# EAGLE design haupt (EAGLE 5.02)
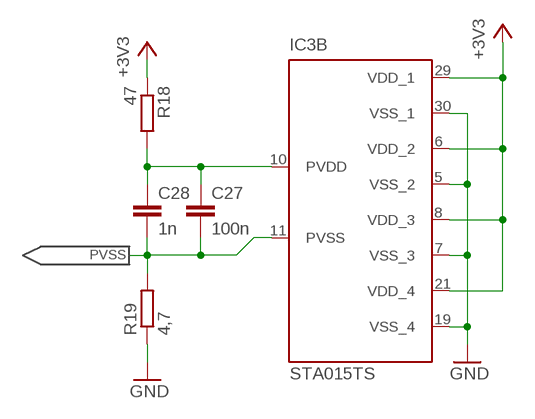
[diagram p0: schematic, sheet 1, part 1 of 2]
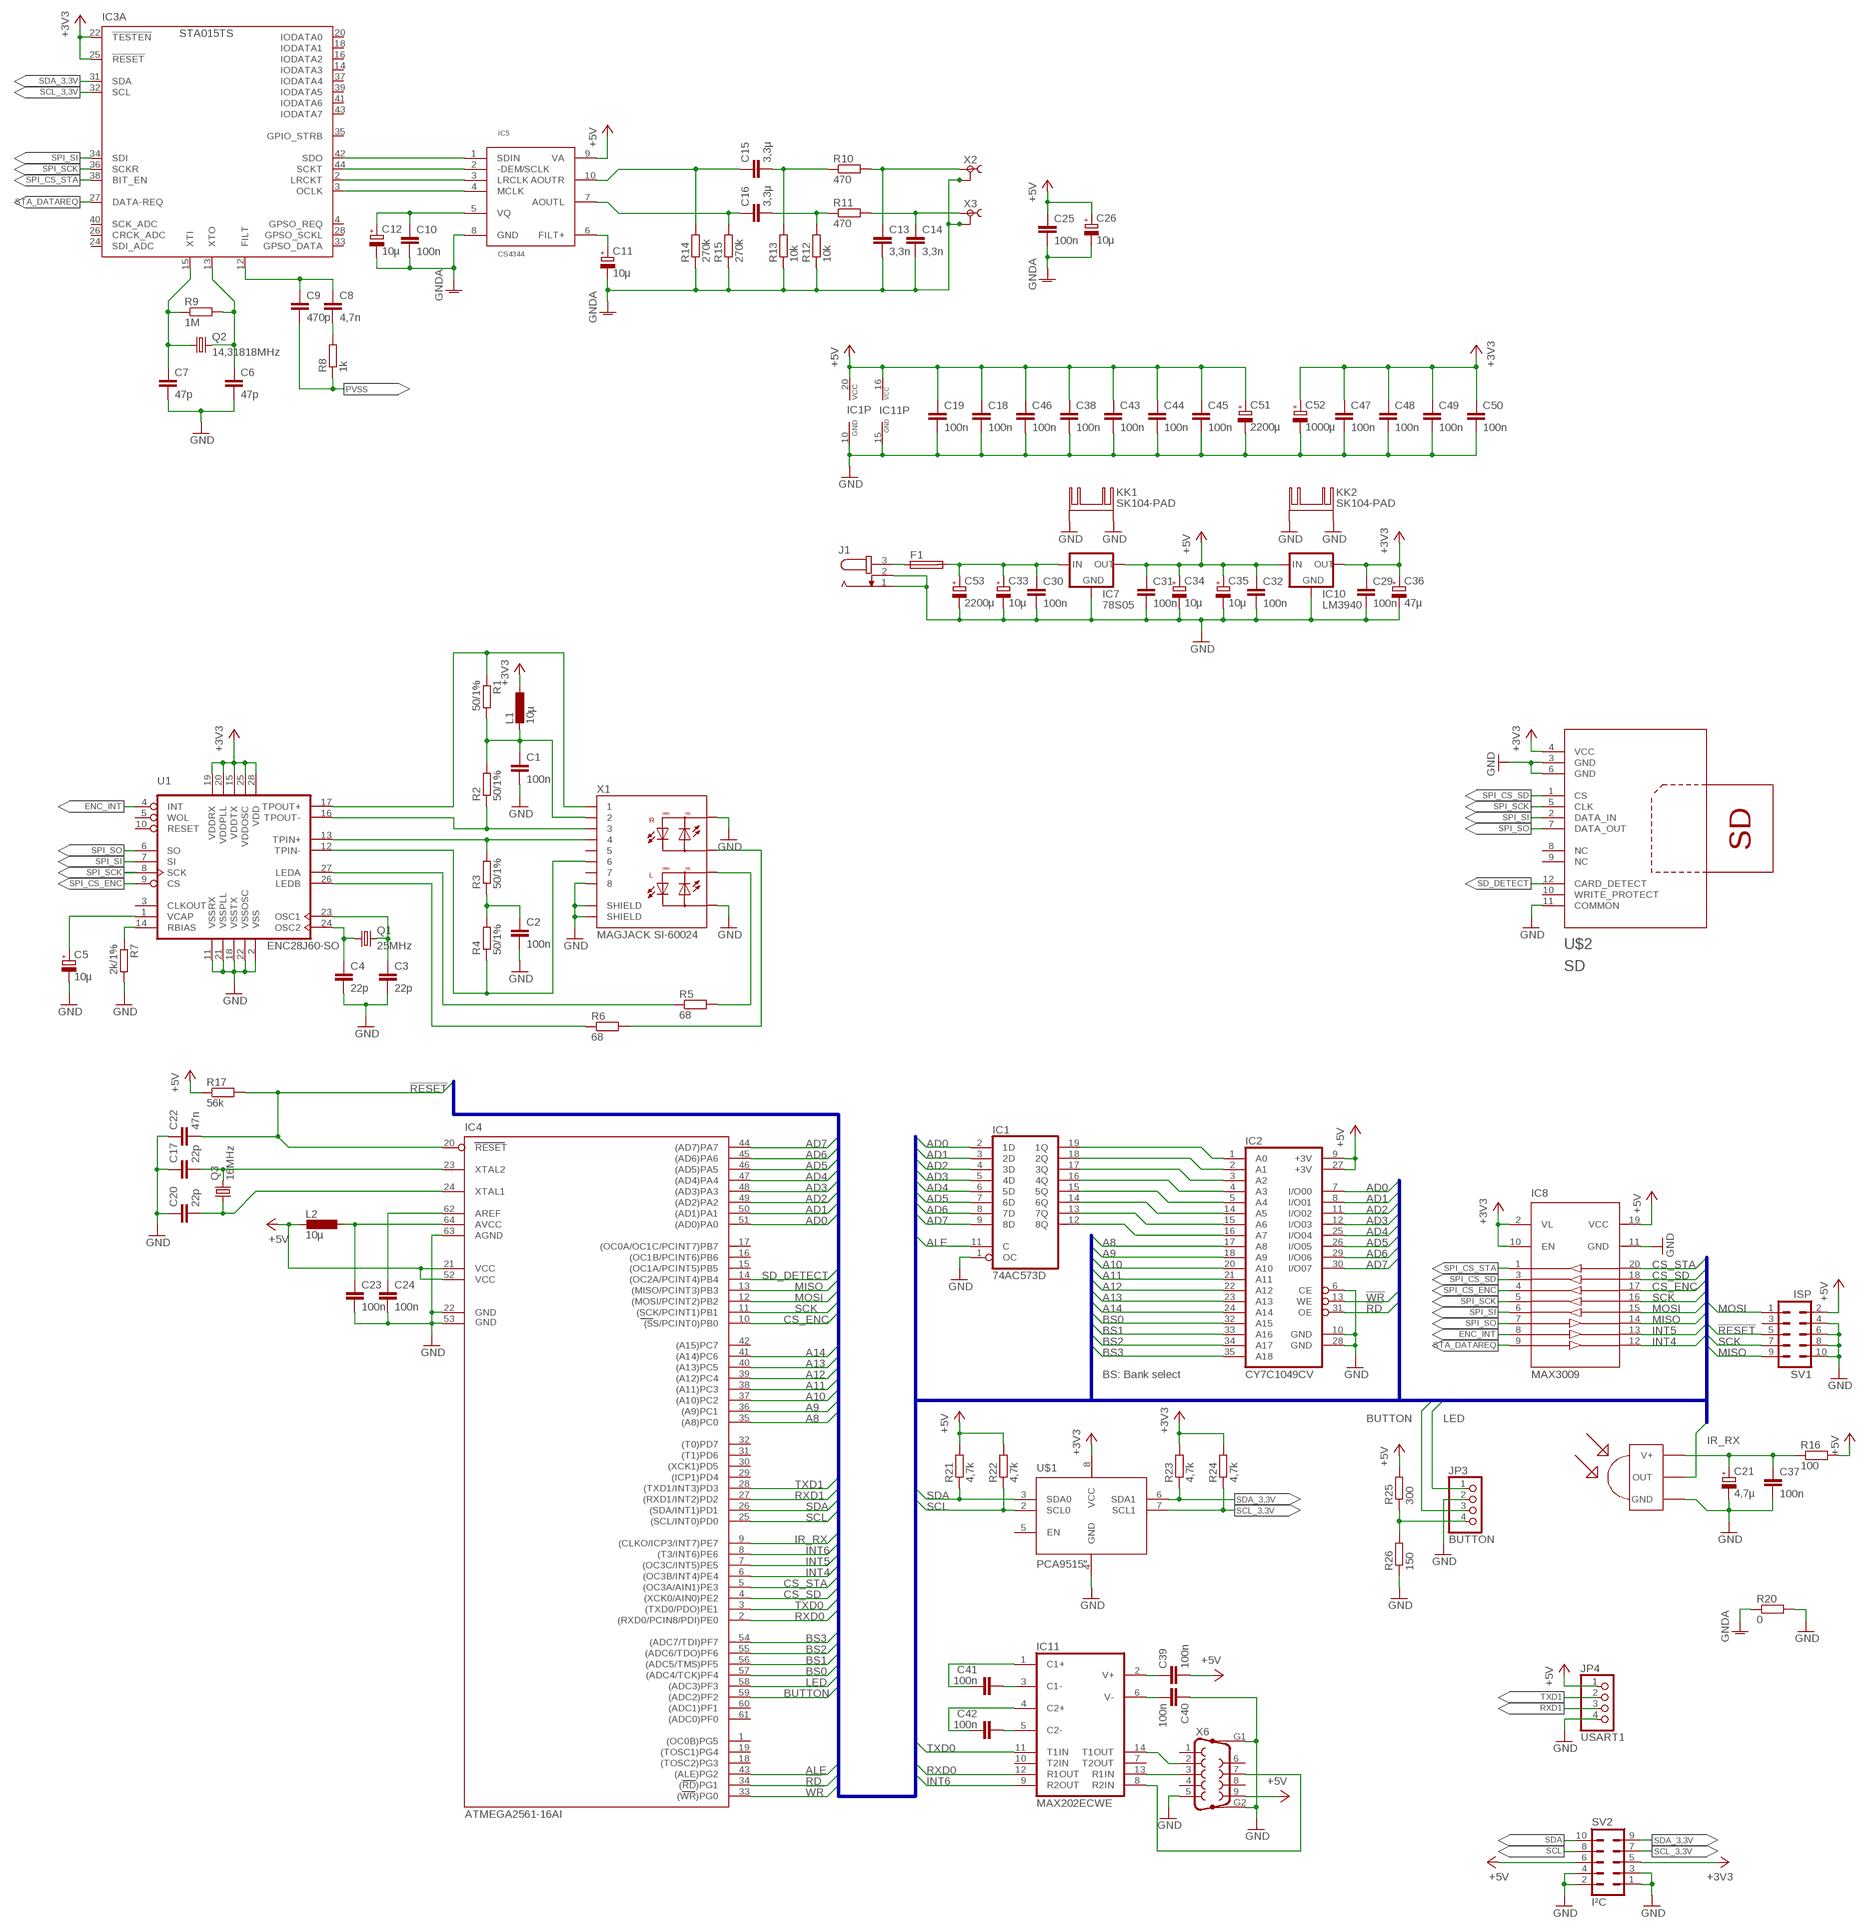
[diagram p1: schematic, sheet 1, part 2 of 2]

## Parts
C1  100n  C-EUC1206  [C1206]
C2  100n  C-EUC1206  [C1206]
C3  22p  C-EUC1206  [C1206]
C4  22p  C-EUC1206  [C1206]
C5  10µ  CPOL-EUE2-5  [E2-5]
C6  47p  C-EUC1206  [C1206]
C7  47p  C-EUC1206  [C1206]
C8  4,7n  C-EUC1206  [C1206]
C9  470p  C-EUC1206  [C1206]
C10  100n  C-EUC1206  [C1206]
C11  10µ  CPOL-EUE2-5  [E2-5]
C12  10µ  CPOL-EUE2-5  [E2-5]
C13  3,3n  C-EUC1206  [C1206]
C14  3,3n  C-EUC1206  [C1206]
C15  3,3µ  C-EUC1206  [C1206]
C16  3,3µ  C-EUC1206  [C1206]
C17  22p  C-EUC1206  [C1206]
C18  100n  C-EUC1206  [C1206]
C19  100n  C-EUC1206  [C1206]
C20  22p  C-EUC1206  [C1206]
C21  4,7µ  CPOL-EUE2-5  [E2-5]
C22  47n  C-EUC1206  [C1206]
C23  100n  C-EUC1206  [C1206]
C24  100n  C-EUC1206  [C1206]
C25  100n  C-EUC1206  [C1206]
C26  10µ  CPOL-EUE2-5  [E2-5]
C27  100n  C-EUC1206  [C1206]
C28  1n  C-EUC1206  [C1206]
C29  100n  C-EUC1206  [C1206]
C30  100n  C-EUC1206  [C1206]
C31  100n  C-EUC1206  [C1206]
C32  100n  C-EUC1206  [C1206]
C33  10µ  CPOL-EUE2-5  [E2-5]
C34  10µ  CPOL-EUE2-5  [E2-5]
C35  10µ  CPOL-EUE2-5  [E2-5]
C36  47µ  CPOL-EUE2-5  [E2-5]
C37  100n  C-EUC1206  [C1206]
C38  100n  C-EUC1206  [C1206]
C39  100n  C-EUC1206  [C1206]
C40  100n  C-EUC1206  [C1206]
C41  100n  C-EUC1206  [C1206]
C42  100n  C-EUC1206  [C1206]
C43  100n  C-EUC1206  [C1206]
C44  100n  C-EUC1206  [C1206]
C45  100n  C-EUC1206  [C1206]
C46  100n  C-EUC1206  [C1206]
C47  100n  C-EUC1206  [C1206]
C48  100n  C-EUC1206  [C1206]
C49  100n  C-EUC1206  [C1206]
C50  100n  C-EUC1206  [C1206]
C51  2200µ  CPOL-EUE5-13  [E5-13]
C52  1000µ  CPOL-EUE5-13  [E5-13]
C53  2200µ  CPOL-EUE5-13  [E5-13]
F1  SH22,5  [SH22,5]
IC1  74AC573D  [SO20W]
IC2  CY7C1049CV  CY7C1049CV33  [SOJV36-400]
IC3  STA015TS  [TQFP44]
IC4  ATMEGA2561-16AI  [TQFP64]
IC5  CS4344  [MSOP10]
IC7  78S05  78XXS  [78XXS]
IC8  MAX3009  [TSSOP20]
IC10  LM3940  78XXS  [78XXS]
IC11  MAX202ECWE  [SO16L]
J1  JACK-PLUG0  [SPC4077]
JP3  BUTTON  PINHD-1X4  [1X04]
JP4  USART1  PINHD-1X4  [1X04]
KK1  SK104-PAD  [SK104-PAD]
KK2  SK104-PAD  [SK104-PAD]
L1  10µ  L-EUL2825P  [L2825P]
L2  10µ  L-EUL2825P  [L2825P]
Q1  25MHz  CRYSTALHC49S  [HC49/S]
Q2  14,31818MHz  CRYSTALHC49S  [HC49/S]
Q3  16MHz  CRYSTALHC49S  [HC49/S]
R1  50/1%  R-EU_0207/2V  [0207/2V]
R2  50/1%  R-EU_0207/2V  [0207/2V]
R3  50/1%  R-EU_0207/2V  [0207/2V]
R4  50/1%  R-EU_0207/2V  [0207/2V]
R5  68  R-EU_R1206  [R1206]
R6  68  R-EU_R1206  [R1206]
R7  2k/1%  R-EU_0207/2V  [0207/2V]
R8  1k  R-EU_R1206  [R1206]
R9  1M  R-EU_R1206  [R1206]
R10  470  R-EU_R1206  [R1206]
R11  470  R-EU_R1206  [R1206]
R12  10k  R-EU_R1206  [R1206]
R13  10k  R-EU_R1206  [R1206]
R14  270k  R-EU_R1206  [R1206]
R15  270k  R-EU_R1206  [R1206]
R16  100  R-EU_R1206  [R1206]
R17  56k  R-EU_R1206  [R1206]
R18  47  R-EU_R1206  [R1206]
R19  4,7  R-EU_R1206  [R1206]
R20  0  R-EU_R1206  [R1206]
R21  4,7k  R-EU_R1206  [R1206]
R22  4,7k  R-EU_R1206  [R1206]
R23  4,7k  R-EU_R1206  [R1206]
R24  4,7k  R-EU_R1206  [R1206]
R25  300  R-EU_R1206  [R1206]
R26  150  R-EU_R1206  [R1206]
SV1  ISP  ML10  [ML10]
SV2  I²C  ML10  [ML10]
U1  ENC28J60-SO  [SO28W]
U$1  PCA9515"  [SO08]
U$2  SD  [SD]
U$3  TSOP1738  [TSOP17XX]
X1  MAGJACK SI-60024  SI-60024  [SI-60024]
X2  TOBU3  [TOBU3]
X3  TOBU3  [TOBU3]
X6  F09HP  [F09HP]

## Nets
!RD: IC2.31(OE) IC4.34((RD)PG1)
!RESET: C22.2 IC4.20(RESET) R17.2 SV1.5
!WR: IC2.13(WE) IC4.33((WR)PG0)
+3V3: C29.1 C36.+ C47.1 C48.1 C49.1 C50.1 C52.+ IC3.6(B:VDD_2) IC3.8(B:VDD_3) IC3.21(B:VDD_4) IC3.22(A:!TESTEN) IC3.25(A:!RESET) IC3.29(B:VDD_1) IC8.2(VL) IC8.10(EN) IC10.OUT L1.1 R18.1 R23.2 R24.2 SV2.5 U1.15(VDDTX) U1.19(VDDRX) U1.20(VDDPLL) U1.25(VDDOSC) U1.28(VDD) U$1.8(VCC) U$2.4(VCC)
+5V: C18.1 C19.1 C25.1 C26.+ C31.1 C32.1 C34.+ C35.+ C38.1 C39.2 C43.1 C44.1 C45.1 C46.1 C51.+ IC1.20(VCC) IC2.9(+3V) IC2.27(+3V) IC4.21(VCC) IC4.52(VCC1) IC5.9(VA) IC7.OUT IC8.19(VCC) IC10.IN IC11.16(VCC) JP4.1 L2.2 R16.2 R17.1 R21.2 R22.2 R25.2 SV1.2 SV2.6 X6.9
A8: IC2.17(A8) IC4.35((A8)PC0)
A9: IC2.18(A9) IC4.36((A9)PC1)
A10: IC2.20(A10) IC4.37((A10)PC2)
A11: IC2.21(A11) IC4.38((A11)PC3)
A12: IC2.22(A12) IC4.39((A12)PC4)
A13: IC2.23(A13) IC4.40((A13)PC5)
A14: IC2.24(A14) IC4.41((A14)PC6)
AD0: IC1.2(1D) IC2.7(I/O00) IC4.51((AD0)PA0)
AD1: IC1.3(2D) IC2.8(I/O01) IC4.50((AD1)PA1)
AD2: IC1.4(3D) IC2.11(I/O02) IC4.49((AD2)PA2)
AD3: IC1.5(4D) IC2.12(I/O03) IC4.48((AD3)PA3)
AD4: IC1.6(5D) IC2.25(I/O04) IC4.47((AD4)PA4)
AD5: IC1.7(6D) IC2.26(I/O05) IC4.46((AD5)PA5)
AD6: IC1.8(7D) IC2.29(I/O06) IC4.45((AD6)PA6)
AD7: IC1.9(8D) IC2.30(I/O07) IC4.44((AD7)PA7)
ALE: IC1.11(C) IC4.43((ALE)PG2)
BS0: IC2.32(A15) IC4.57((ADC4/TCK)PF4)
BS1: IC2.33(A16) IC4.56((ADC5/TMS)PF5)
BS2: IC2.34(A17) IC4.55((ADC6/TDO)PF6)
BS3: IC2.35(A18) IC4.54((ADC7/TDI)PF7)
BUTTON: IC4.59((ADC2)PF2) JP3.3
CS_ENC: IC4.10((SS/PCINT0)PB0) IC8.17(VCC3)
CS_SD: IC4.4((XCK0/AIN0)PE2) IC8.18(VCC2)
CS_STA: IC4.5((OC3A/AIN1)PE3) IC8.20(VCC1)
ENC_INT: IC8.8(VL7) U1.4(INT)
GND: C1.2 C2.2 C3.2 C4.2 C5.- C6.2 C7.2 C17.1 C18.2 C19.2 C20.1 C21.- C22.1 C23.2 C24.2 C29.2 C30.2 C31.2 C32.2 C33.- C34.- C35.- C36.- C37.2 C38.2 C40.1 C43.2 C44.2 C45.2 C46.2 C47.2 C48.2 C49.2 C50.2 C51.- C52.- C53.- IC1.1(OC) IC1.10(GND) IC2.6(CE) IC2.10(GND) IC2.28(GND) IC3.5(B:VSS_2) IC3.7(B:VSS_3) IC3.19(B:VSS_4) IC3.30(B:VSS_1) IC4.22(GND) IC4.53(GND1) IC4.63(AGND) IC7.GND IC8.11(GND) IC10.GND IC11.15(GND) J1.1 J1.2 JP3.2 JP4.4 KK1.K1(K) KK1.K2(K) KK2.K1(K) KK2.K2(K) R7.2 R19.1 R20.2 R26.1 SV1.4 SV1.6 SV1.8 SV1.10 SV2.1 SV2.2 SV2.3 SV2.4 U1.2(VSS) U1.11(VSSRX) U1.18(VSSTX) U1.21(VSSPLL) U1.22(VSSOSC) U$1.4(GND) U$2.3(GND) U$2.6(GND) U$2.11(COMMON) U$3.GND X1.8 X1.L_YEL_A X1.R_GRN_A X1.SCHIELD@2(SHIELD) X1.SHIELD@1(SHIELD) X6.5 X6.G1 X6.G2
GNDA: C10.2 C11.- C12.- C13.2 C14.2 C25.2 C26.- IC5.8(GND) R12.1 R13.1 R14.1 R15.1 R20.1 X2.2 X2.2@1 X2.2@2 X3.2 X3.2@1 X3.2@2
INT4: IC4.6((OC3B/INT4)PE4) IC8.12(VCC8)
INT5: IC4.7((OC3C/INT5)PE5) IC8.13(VCC7)
INT6: IC4.8((T3/INT6)PE6) IC11.9(R2OUT)
IR_RX: IC4.9((CLKO/ICP3/INT7)PE7) U$3.OUT
LED: IC4.58((ADC3)PF3) JP3.1
MISO: IC4.13((MISO/PCINT3)PB3) IC8.14(VCC6) SV1.9
MOSI: IC4.12((MOSI/PCINT2)PB2) IC8.15(VCC5) SV1.1
N$1: IC1.19(1Q) IC2.1(A0)
N$2: IC1.18(2Q) IC2.2(A1)
N$3: IC1.17(3Q) IC2.3(A2)
N$4: IC1.16(4Q) IC2.4(A3)
N$5: IC1.15(5Q) IC2.5(A4)
N$6: IC1.14(6Q) IC2.14(A5)
N$7: IC1.13(7Q) IC2.15(A6)
N$8: IC1.12(8Q) IC2.16(A7)
N$9: R1.1 U1.17(TPOUT+) X1.1
N$10: R2.1 U1.16(TPOUT-) X1.3
N$11: R3.2 U1.13(TPIN+) X1.4
N$12: R4.1 U1.12(TPIN-) X1.6
N$13: C1.1 L1.2 R1.2 R2.2 X1.2
N$14: R6.2 X1.R_YEL_A
N$15: C2.1 R3.1 R4.2
N$16: R5.1 U1.27(LEDA)
N$17: R6.1 U1.26(LEDB)
N$18: R5.2 X1.L_GRN_A
N$19: C4.1 Q1.1 U1.24(OSC2)
N$20: C3.1 Q1.2 U1.23(OSC1)
N$21: R7.1 U1.14(RBIAS)
N$22: C5.+ U1.1(VCAP)
N$23: F1.1 J1.3
N$24: IC11.8(R2IN) X6.7
N$25: C7.1 IC3.15(A:XTI) Q2.1 R9.1
N$26: C6.1 IC3.13(A:XTO) Q2.2 R9.2
N$27: C8.1 C9.1 IC3.12(A:FILT)
N$28: IC3.42(A:SDO) IC5.1(SDIN)
N$29: IC3.44(A:SCKT) IC5.2(-DEM/SCLK)
N$30: IC3.2(A:LRCKT) IC5.3(LRCLK)
N$31: IC3.3(A:OCLK) IC5.4(MCLK)
N$32: C8.2 R8.2
N$33: C10.1 C12.+ IC5.5(VQ)
N$34: C11.+ IC5.6(FILT+)
N$35: C14.1 R11.2 X3.1
N$36: C13.1 R10.2 X2.1
N$37: C17.2 IC4.23(XTAL2) Q3.2
N$38: C15.2 R10.1 R13.2
N$39: C16.2 R11.1 R12.2
N$40: C15.1 IC5.10(AOUTR) R14.2
N$41: C16.1 IC5.7(AOUTL) R15.2
N$42: JP3.4 R25.1 R26.2
N$44: C20.2 IC4.24(XTAL1) Q3.1
N$45: C21.+ C37.1 R16.1 U$3.V+
N$47: C23.1 IC4.64(AVCC) L2.1
N$48: C27.1 C28.1 IC3.10(B:PVDD) R18.2
N$49: C24.1 IC4.62(AREF)
N$51: C30.1 C33.+ C53.+ F1.2 IC7.IN
N$56: C41.2 IC11.1(C1+)
N$57: C41.1 IC11.3(C1-)
N$58: C42.2 IC11.4(C2+)
N$59: C42.1 IC11.5(C2-)
N$60: C39.1 IC11.2(V+)
N$61: C40.2 IC11.6(V-)
N$62: IC11.14(T1OUT) X6.2
N$63: IC11.13(R1IN) X6.3
PVSS: C9.2 C27.2 C28.2 IC3.11(B:PVSS) R8.1 R19.2
RXD0: IC4.2((RXD0/PCIN8/PDI)PE0) IC11.12(R1OUT)
RXD1: IC4.27((RXD1/INT2)PD2) JP4.3
SCK: IC4.11((SCK/PCINT1)PB1) IC8.16(VCC4) SV1.7
SCL: IC4.25((SCL/INT0)PD0) R22.1 SV2.8 U$1.2(SCL0)
SCL_3,3V: IC3.32(A:SCL) R24.1 SV2.7 U$1.7(SCL1)
SD_DETECT: IC4.14((OC2A/PCINT4)PB4) U$2.12(CARD_DETECT)
SDA: IC4.26((SDA/INT1)PD1) R21.1 SV2.10 U$1.3(SDA0)
SDA_3,3V: IC3.31(A:SDA) R23.1 SV2.9 U$1.6(SDA1)
SPI_CS_ENC: IC8.4(VL3) U1.9(CS)
SPI_CS_SD: IC8.3(VL2) U$2.1(CS)
SPI_CS_STA: IC3.38(A:BIT_EN) IC8.1(VL1)
SPI_SCK: IC3.36(A:SCKR) IC8.5(VL4) U1.8(SCK) U$2.5(CLK)
SPI_SI: IC3.34(A:SDI) IC8.6(VL5) U1.7(SI) U$2.2(DATA_IN)
SPI_SO: IC8.7(VL6) U1.6(SO) U$2.7(DATA_OUT)
STA_DATAREQ: IC3.27(A:DATA-REQ) IC8.9(VL8)
TXD0: IC4.3((TXD0/PDO)PE1) IC11.11(T1IN)
TXD1: IC4.28((TXD1/INT3)PD3) JP4.2
Unconnected: IC3.1(NC1:NC) IC3.4(A:GPSO_REQ) IC3.9(NC2:NC) IC3.14(A:IODATA3) IC3.16(A:IODATA2) IC3.17(NC3:NC) IC3.18(A:IODATA1) IC3.20(A:IODATA0) IC3.23(NC4:NC) IC3.24(A:SDI_ADC) IC3.26(A:CRCK_ADC) IC3.28(A:GPSO_SCKL) IC3.33(A:GPSO_DATA) IC3.35(A:GPIO_STRB) IC3.37(A:IODATA4) IC3.39(A:IODATA5) IC3.40(A:SCK_ADC) IC3.41(A:IODATA6) IC3.43(A:IODATA7) IC4.1((OC0B)PG5) IC4.15((OC1A/PCINT5)PB5) IC4.16((OC1B/PCINT6)PB6) IC4.17((OC0A/OC1C/PCINT7)PB7) IC4.18((TOSC2)PG3) IC4.19((TOSC1)PG4) IC4.29((ICP1)PD4) IC4.30((XCK1)PD5) IC4.31((T1)PD6) IC4.32((T0)PD7) IC4.42((A15)PC7) IC4.60((ADC1)PF1) IC4.61((ADC0)PF0) IC11.7(T2OUT) IC11.10(T2IN) SV1.3 U1.3(CLKOUT) U1.5(WOL) U1.10(RESET) U$1.5(EN) U$2.8(NC) U$2.9(NC) U$2.10(WRITE_PROTECT) X1.5 X1.7 X6.1 X6.4 X6.6 X6.8

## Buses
AD[0..7],ALE,!RD,!WR,A[8..14],BS[0..3],MOSI,MISO,SCK,SDA,SCL,RXD0,TXD0,RXD1,TXD1,CS_STA,CS_SD,CS_ENC,!RESET,INT2,INT4,INT5,INT6,IR_RX,SD_DETECT,LED,BUTTON

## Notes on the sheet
- BS: Bank select

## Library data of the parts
C1-C4 C6-C10 C13-C20 C22-C25 C27-C32 C37-C50 = rcl:C-EU: CAPACITOR, European symbol
C5 C11 C12 C21 C26 C33-C36 C51-C53 = rcl:CPOL-EU: POLARIZED CAPACITOR, European symbol
F1 = fuse:SH22,5: FUSE HOLDER
IC1 = 74xx-eu:74*573: 8-bit D latch BUS DRIVER
IC2 = memory-sram:CY7C1049CV33: 4-Mbit (512K x 8) Static RAM Source: CYPRESS cy7c1049cv33_8.pdf
IC3 = st-microelectronics:STA015TS: MP3 AUDIO DECODER with ADPCM capability
IC4 = atmel-2005:ATMEGA2561*: MICROCONTROLLER 256 Kbytes FLASH 4 Kbytes EEPROM 8 Kbytes SRAM 54 General Purpose I/O pins 6-channels 16-bit PWM 2 x Serial USARTs 8-channels 10-bit A/D
IC5 = cirrus-3:CS4344
IC7 IC10 = v-reg:78XXS: VOLTAGE REGULATOR
IC8 = maxim:MAX3009: +1.2V to +5.5V, ±15kV ESD-Protected, 0.1?A, 35Mbps, 8-Channel Level Translators
IC11 = maxim:MAX202ECWE: RS232 TRANSEIVER
J1 = con-jack:JACK-PLUG: DC POWER JACK Power Jack, DC, Right Angle, Through Hole, Rated 5A at 16VDC, PC Terminals Distributor: Farnell (www.Farnell.de) Drawing: 84N1161.pdf / 84N1162.pdf Manufacturer: SPC Technology (www.spctechnology.com) Type: SPC4077 / SPC 4078
JP3 JP4 = pinhead:PINHD-1X4: PIN HEADER
KK1 KK2 = heatsink:SK104-PAD: HEATSINK
L1 L2 = rcl:L-EU: INDUCTOR, European symbol
Q1-Q3 = crystal:CRYSTAL: CRYSTAL
R1-R26 = rcl:R-EU_: RESISTOR, European symbol
SV1 SV2 = con-harting-ml:ML10: HARTING
U1 = microchip-enc28j60:ENC28J60-*: Microchip 10Mbit Eth. contoller with SPI interface
U$1 = micro-philips:PCA9515: I2C bus repeater
U$2 = sd:SD
U$3 = tsop:TSOP1738: IR Receiver and Demodulator
X1 = si-50014:SI-60024
X2 X3 = con-hirschmann:TOBU3: Female Cinch CONNECTOR ( RCA Jack )
X6 = con-subd:F09HP: SUB-D

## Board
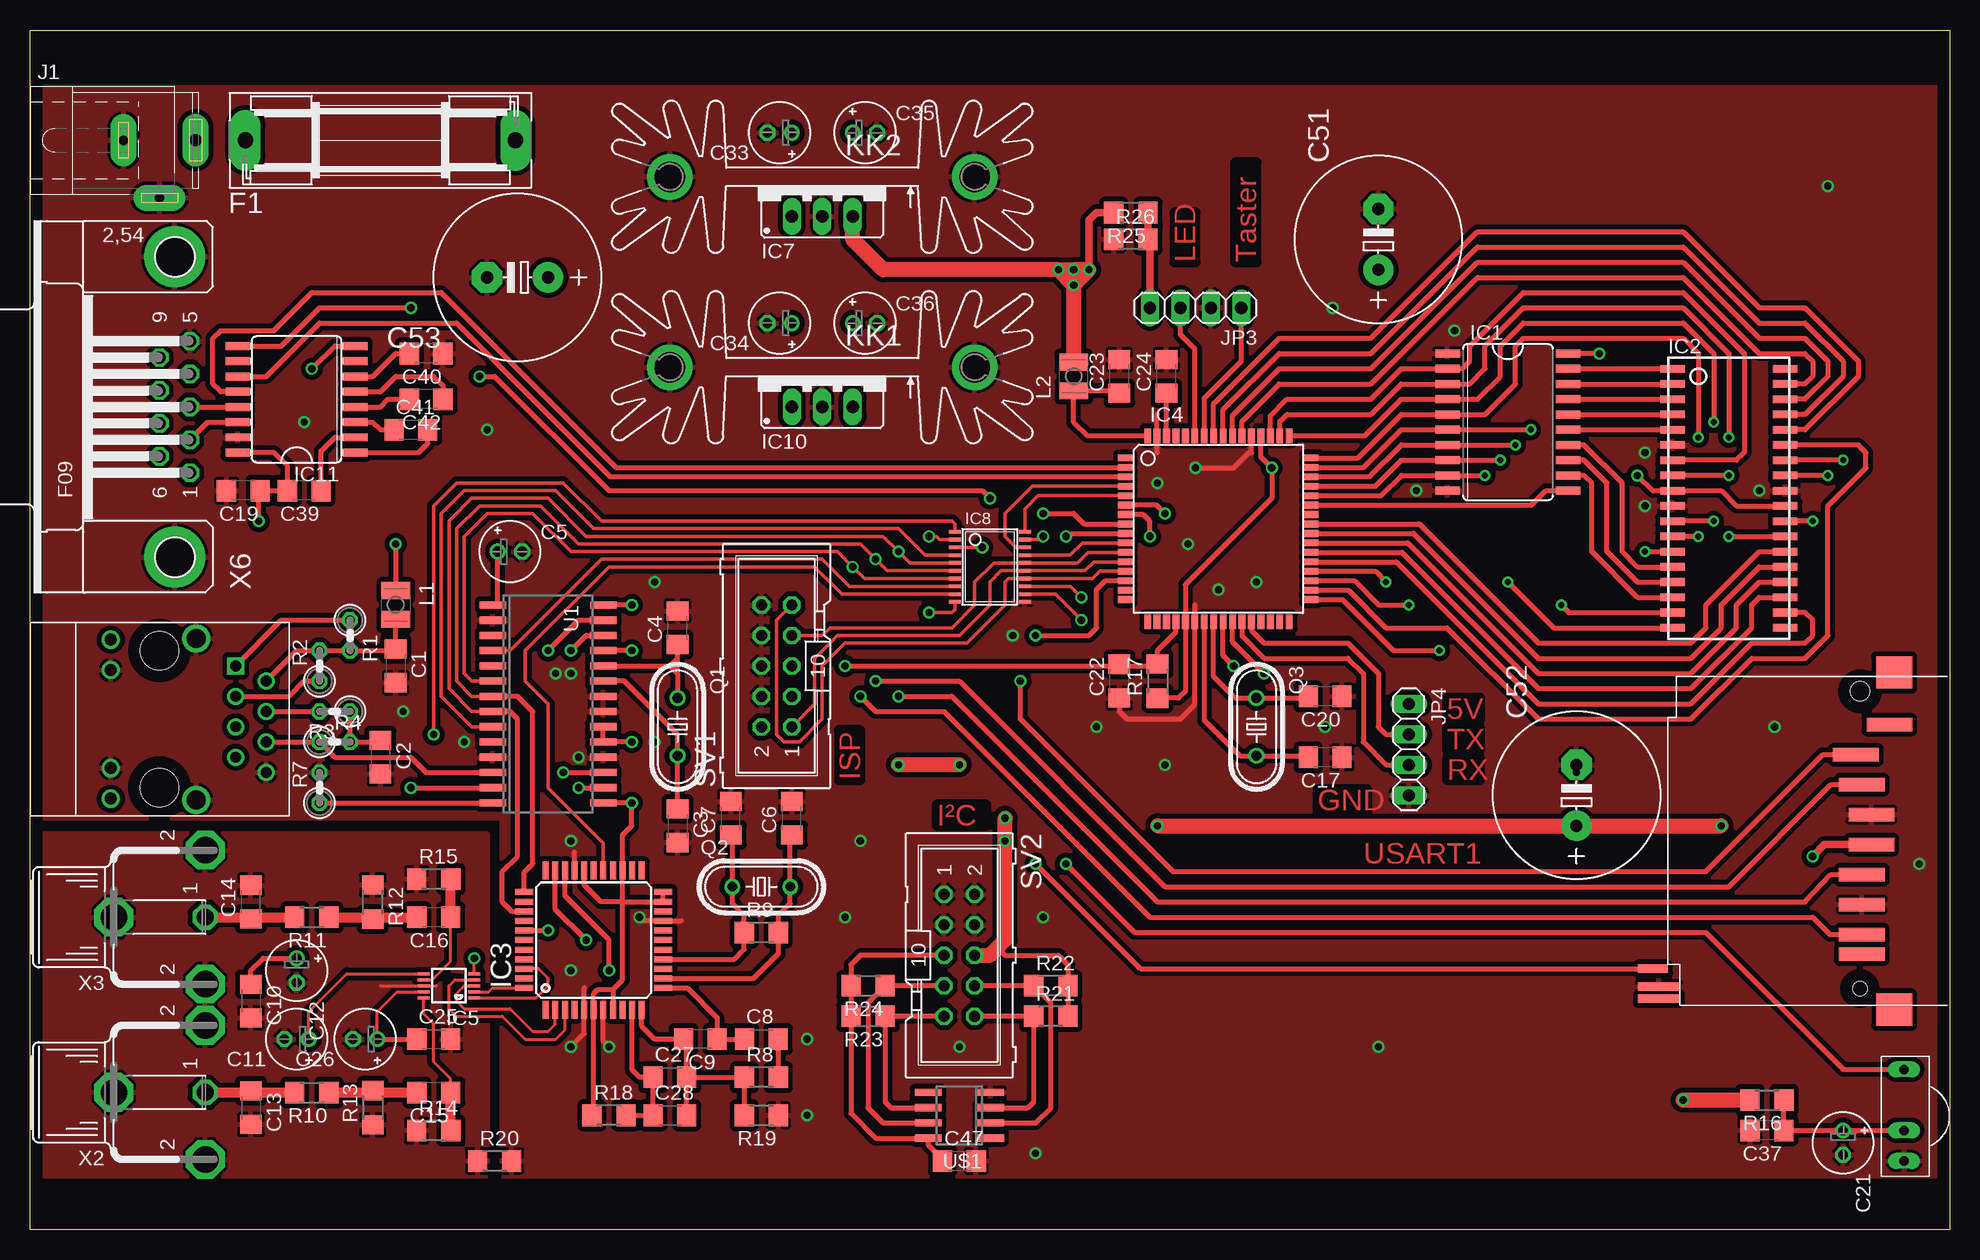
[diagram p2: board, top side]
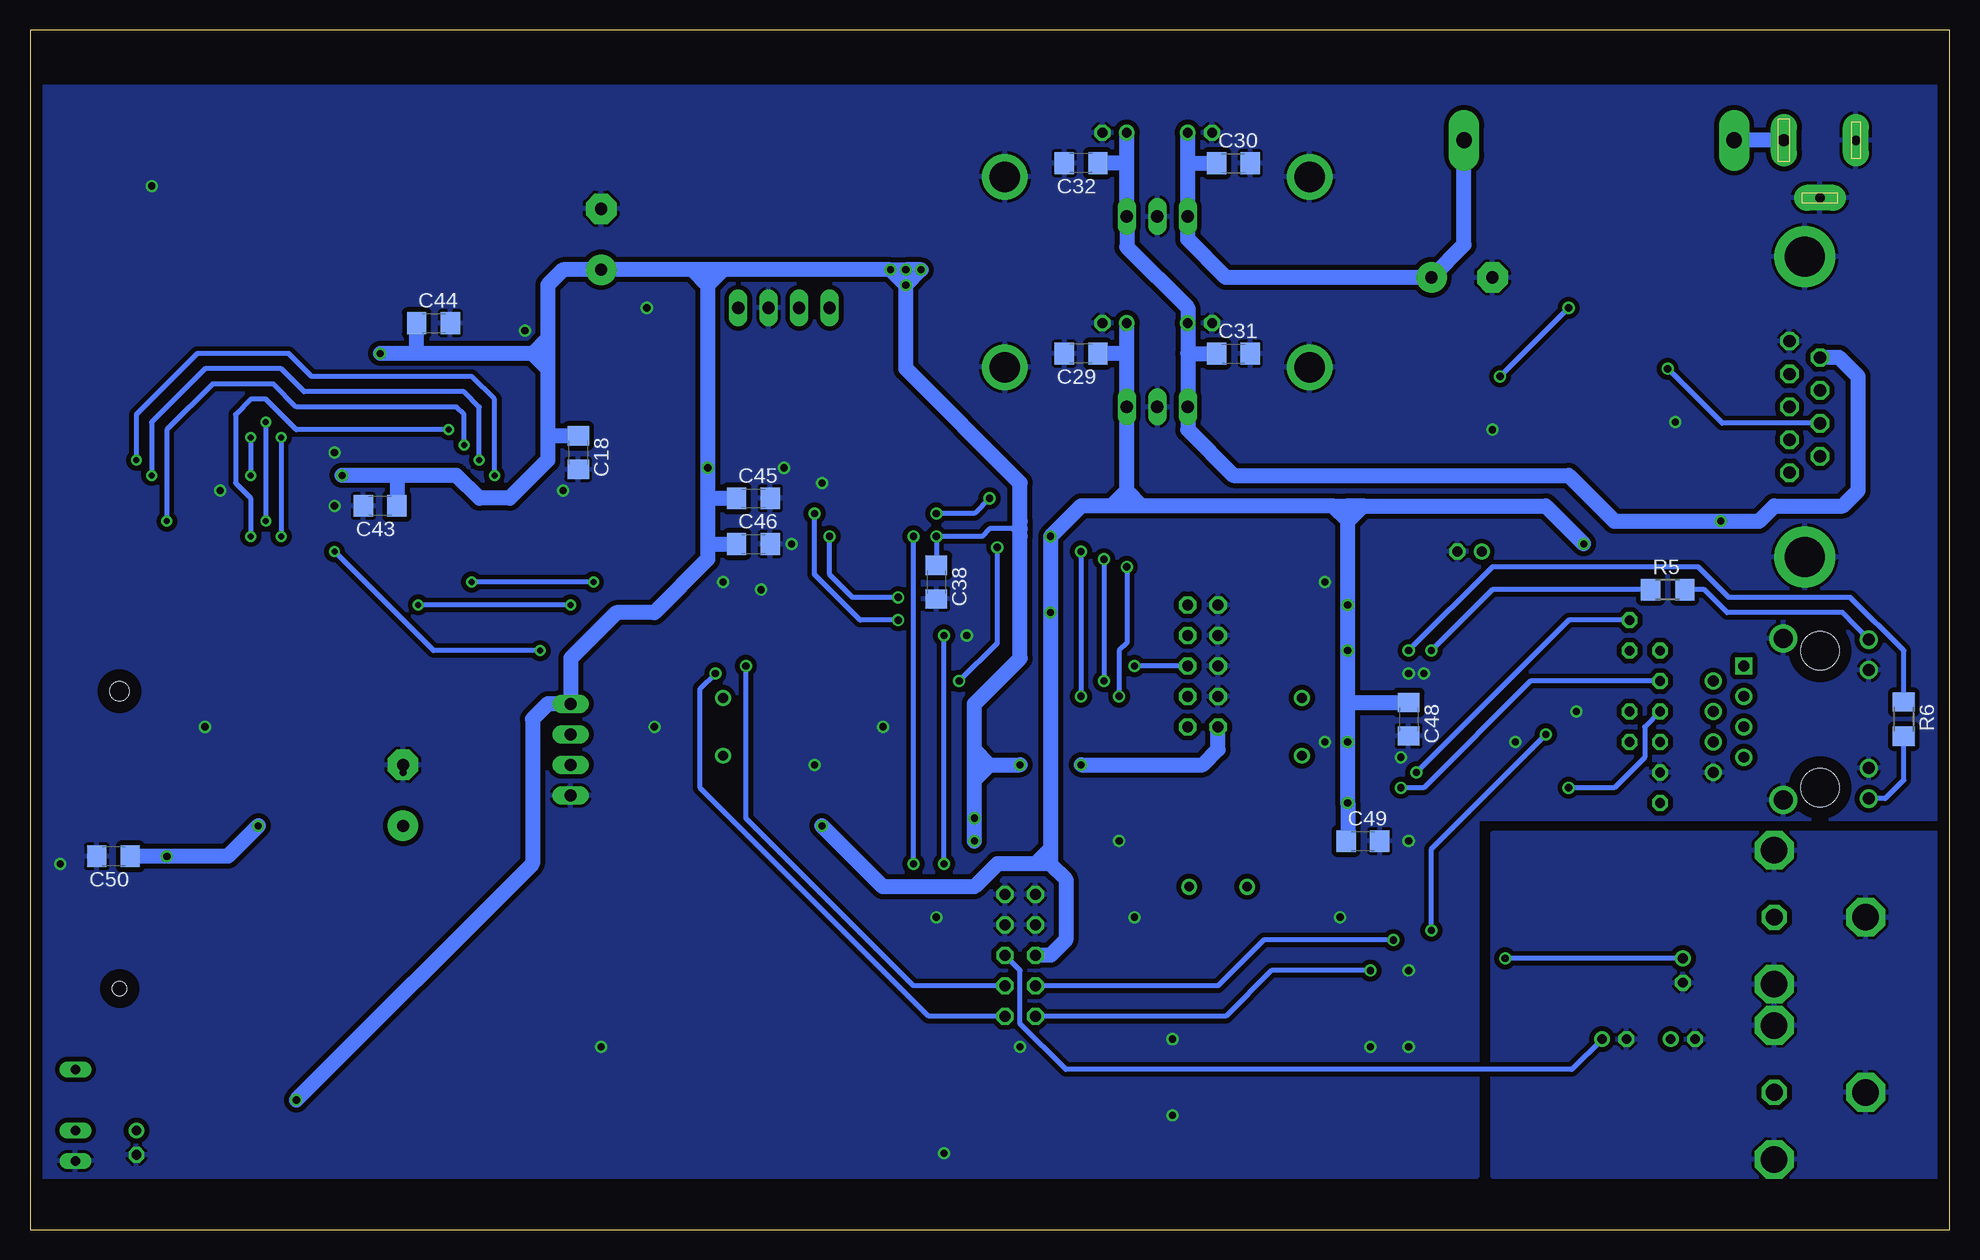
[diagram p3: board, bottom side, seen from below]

Size 160 x 100 mm. Coordinates in mm from the lower left corner, seen from the top.
Outline: 0,0 0,100 160,100 160,0 0,0
Copper layers (1*16): Top 0.035mm / dielectric 1.5mm / Bottom 0.035mm
Design rules "default *": minimum track width 10mil, minimum drill 24mil, track to track 8mil, track to pad 8mil, pad to pad 8mil, via to via 8mil, smd to smd 8mil, copper to edge 40mil, drill to drill 8mil, minimum pad ring 10mil, minimum via ring 8mil, stop-mask expansion 4mil, vias tented up to drill 0mil, thermal gap 10mil

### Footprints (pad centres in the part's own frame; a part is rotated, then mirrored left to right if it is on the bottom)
C1206 = smd 1.6 x 1.8: 1 -1.4,0; 2 1.4,0
E2-5 = drill 0.813 pad 1.27 round: + -1.016,0 | drill 0.813 pad 1.27 octagon: - 1.016,0
E5-13 = drill 1.016 pad 2.54 round: + -2.54,0 | drill 1.016 pad 2.54 octagon: - 2.54,0
SH22,5 = drill 1.321 pad 2.54 long: 1 -11.252,0; 2 11.252,0
SO20W = smd 0.66 x 2.032: 1 -5.715,-5.029; 2 -4.445,-5.029; 3 -3.175,-5.029; 4 -1.905,-5.029; 5 -0.635,-5.029; 6 0.635,-5.029; 7 1.905,-5.029; 8 3.175,-5.029; 9 4.445,-5.029; 10 5.715,-5.029; 11 5.715,5.029; 12 4.445,5.029; 13 3.175,5.029; 14 1.905,5.029; 15 0.635,5.029; 16 -0.635,5.029; 17 -1.905,5.029; 18 -3.175,5.029; 19 -4.445,5.029; 20 -5.715,5.029
SOJV36-400 = smd 0.635 x 2.032: 1 -10.795,-4.699; 2 -9.525,-4.699; 3 -8.255,-4.699; 4 -6.985,-4.699; 5 -5.715,-4.699; 6 -4.445,-4.699; 7 -3.175,-4.699; 8 -1.905,-4.699; 9 -0.635,-4.699; 10 0.635,-4.699; 11 1.905,-4.699; 12 3.175,-4.699; 13 4.445,-4.699; 14 5.715,-4.699; 15 6.985,-4.699; 16 8.255,-4.699; 17 9.525,-4.699; 18 10.795,-4.699; 19 10.795,4.699; 20 9.525,4.699; 21 8.255,4.699; 22 6.985,4.699; 23 5.715,4.699; 24 4.445,4.699; 25 3.175,4.699; 26 1.905,4.699; 27 0.635,4.699; 28 -0.635,4.699; 29 -1.905,4.699; 30 -3.175,4.699; 31 -4.445,4.699; 32 -5.715,4.699; 33 -6.985,4.699; 34 -8.255,4.699; 35 -9.525,4.699; 36 -10.795,4.699
TQFP44 = smd 1.5 x 0.5: 1 -5.8,4; 2 -5.8,3.2; 3 -5.8,2.4; 4 -5.8,1.6; 5 -5.8,0.8; 6 -5.8,0; 7 -5.8,-0.8; 8 -5.8,-1.6; 9 -5.8,-2.4; 10 -5.8,-3.2; 11 -5.8,-4; 23 5.8,-4; 24 5.8,-3.2; 25 5.8,-2.4; 26 5.8,-1.6; 27 5.8,-0.8; 28 5.8,0; 29 5.8,0.8; 30 5.8,1.6; 31 5.8,2.4; 32 5.8,3.2; 33 5.8,4 | smd 0.5 x 1.5: 12 -4,-5.8; 13 -3.2,-5.8; 14 -2.4,-5.8; 15 -1.6,-5.8; 16 -0.8,-5.8; 17 0,-5.8; 18 0.8,-5.8; 19 1.6,-5.8; 20 2.4,-5.8; 21 3.2,-5.8; 22 4,-5.8; 34 4,5.8; 35 3.2,5.8; 36 2.4,5.8; 37 1.6,5.8; 38 0.8,5.8; 39 0,5.8; 40 -0.8,5.8; 41 -1.6,5.8; 42 -2.4,5.8; 43 -3.2,5.8; 44 -4,5.8
TQFP64 = smd 1.194 x 0.559: 1 -7.76,5.905; 2 -7.76,5.118; 3 -7.76,4.331; 4 -7.76,3.543; 5 -7.76,2.756; 6 -7.76,1.968; 7 -7.76,1.181; 8 -7.76,0.394; 9 -7.76,-0.394; 10 -7.76,-1.181; 11 -7.76,-1.968; 12 -7.76,-2.756; 13 -7.76,-3.543; 14 -7.76,-4.331; 15 -7.76,-5.118; 16 -7.76,-5.905; 33 7.76,-5.905; 34 7.76,-5.118; 35 7.76,-4.331; 36 7.76,-3.543; 37 7.76,-2.756; 38 7.76,-1.968; 39 7.76,-1.181; 40 7.76,-0.394; 41 7.76,0.394; 42 7.76,1.181; 43 7.76,1.968; 44 7.76,2.756; 45 7.76,3.543; 46 7.76,4.331; 47 7.76,5.118; 48 7.76,5.905 | smd 0.559 x 1.194: 17 -5.905,-7.76; 18 -5.118,-7.76; 19 -4.331,-7.76; 20 -3.543,-7.76; 21 -2.756,-7.76; 22 -1.968,-7.76; 23 -1.181,-7.76; 24 -0.394,-7.76; 25 0.394,-7.76; 26 1.181,-7.76; 27 1.968,-7.76; 28 2.756,-7.76; 29 3.543,-7.76; 30 4.331,-7.76; 31 5.118,-7.76; 32 5.905,-7.76; 49 5.905,7.76; 50 5.118,7.76; 51 4.331,7.76; 52 3.543,7.76; 53 2.756,7.76; 54 1.968,7.76; 55 1.181,7.76; 56 0.394,7.76; 57 -0.394,7.76; 58 -1.181,7.76; 59 -1.968,7.76; 60 -2.756,7.76; 61 -3.543,7.76; 62 -4.331,7.76; 63 -5.118,7.76; 64 -5.905,7.76
MSOP10 = smd 0.25 x 1: 1 -1,-2.113; 2 -0.5,-2.113; 3 0,-2.113; 4 0.5,-2.113; 5 1,-2.113; 6 1,2.113; 7 0.5,2.113; 8 0,2.113; 9 -0.5,2.113; 10 -1,2.113
78XXS = drill 1.016 long: GND 0,-2.54; IN -2.54,-2.54; OUT 2.54,-2.54
TSSOP20 = smd 0.305 x 0.991: 1 -2.925,-2.918; 2 -2.275,-2.918; 3 -1.625,-2.918; 4 -0.975,-2.918; 5 -0.325,-2.918; 6 0.325,-2.918; 7 0.975,-2.918; 8 1.625,-2.918; 9 2.275,-2.918; 10 2.925,-2.918; 11 2.925,2.918; 12 2.275,2.918; 13 1.625,2.918; 14 0.975,2.918; 15 0.325,2.918; 16 -0.325,2.918; 17 -0.975,2.918; 18 -1.625,2.918; 19 -2.275,2.918; 20 -2.925,2.918
SO16L = smd 0.66 x 2.032: 1 -4.445,-4.902; 2 -3.175,-4.902; 3 -1.905,-4.902; 4 -0.635,-4.902; 5 0.635,-4.902; 6 1.905,-4.902; 7 3.175,-4.902; 8 4.445,-4.902; 9 4.445,4.902; 10 3.175,4.902; 11 1.905,4.902; 12 0.635,4.902; 13 -0.635,4.902; 14 -1.905,4.902; 15 -3.175,4.902; 16 -4.445,4.902
SPC4077 = drill 0.8 pad 2.184 long: 1 -3,0; 2 0,-4.8 | drill 1 pad 2.184 long: 3 3,0
1X04 = drill 1.016 long: 1 -3.81,0; 2 -1.27,0; 3 1.27,0; 4 3.81,0
SK104-PAD = drill 2.54 pad 3.81 round: K1 -12.7,-0.762; K2 12.7,-0.762
L2825P = smd 1.4 x 2.4: 1 -1.2,0; 2 1.2,0
HC49/S = drill 0.813 round: 1 -2.413,0; 2 2.413,0
0207/2V = drill 0.813 octagon: 1 -1.27,0; 2 1.27,0
R1206 = smd 1.6 x 1.803: 1 -1.422,0; 2 1.422,0
ML10 = drill 0.914 octagon: 1 -5.08,-1.27; 2 -5.08,1.27; 3 -2.54,-1.27; 4 -2.54,1.27; 5 0,-1.27; 6 0,1.27; 7 2.54,-1.27; 8 2.54,1.27; 9 5.08,-1.27; 10 5.08,1.27
SO28W = smd 0.6 x 2.2: 1 -8.255,-4.6; 2 -6.985,-4.6; 3 -5.715,-4.6; 4 -4.445,-4.6; 5 -3.175,-4.6; 6 -1.905,-4.6; 7 -0.635,-4.6; 8 0.635,-4.6; 9 1.905,-4.6; 10 3.175,-4.6; 11 4.445,-4.6; 12 5.715,-4.6; 13 6.985,-4.6; 14 8.255,-4.6; 15 8.255,4.6; 16 6.985,4.6; 17 5.715,4.6; 18 4.445,4.6; 19 3.175,4.6; 20 1.905,4.6; 21 0.635,4.6; 22 -0.635,4.6; 23 -1.905,4.6; 24 -3.175,4.6; 25 -4.445,4.6; 26 -5.715,4.6; 27 -6.985,4.6; 28 -8.255,4.6
SO08 = smd 0.6 x 2.2: 1 -1.905,-2.6; 2 -0.635,-2.6; 3 0.635,-2.6; 4 1.905,-2.6; 5 1.905,2.6; 6 0.635,2.6; 7 -0.635,2.6; 8 -1.905,2.6
SD = smd 1.1 x 3.8: 1 7.2,-15.66; 2 4.7,-16.16; 3 2.2,-16.96; 4 -0.3,-16.96; 5 -2.8,-16.16; 6 -5.3,-16.16; 7 -7.8,-16.16; 8 -9.43,-16.16; 9 9.7,-18.46 | smd 0.7 x 3.5: 10 -13.15,0.75; 11 -12.15,0.75 | smd 0.7 x 2.5: 12 -10.65,1.25 | smd 2.7 x 3: P$1 -14.05,-18.85; P$2 14.05,-18.85 | hole 1.2: -12.3,-16 | hole 1.6: 12.5,-16
TSOP17XX = drill 0.813 long: GND -3.81,0; OUT 3.81,0; V+ -1.27,0
SI-60024 = drill 0.9 square: 1 -4.445,6.35 | drill 0.9 round: 2 -3.175,8.89; 3 -1.905,6.35; 4 -0.635,8.89; 5 0.635,6.35; 6 1.905,8.89; 7 3.175,6.35; 8 4.445,8.89 | drill 1 round: L_GRN_A -6.625,-4.06; L_YEL_A -4.085,-4.06; R_GRN_A 4.085,-4.06; R_YEL_A 6.625,-4.06 | drill 1.57 round: SCHIELD@2 6.73,3.05; SHIELD@1 -6.73,3.05 | hole 3.2: -5.715,0; 5.715,0
TOBU3 = drill 1.397 octagon: 1 0,-2.54 | drill 2.21 octagon: 2 5.588,-2.54; 2@1 -5.588,-2.54; 2@2 0,5.08
F09HP = drill 1.016 octagon: 1 -5.486,-1.27; 2 -2.743,-1.27; 3 0,-1.27; 4 2.743,-1.27; 5 5.486,-1.27; 6 -4.115,1.27; 7 -1.372,1.27; 8 1.372,1.27; 9 4.115,1.27 | drill 3.302 pad 5.08 round: G1 -12.522,0; G2 12.522,0

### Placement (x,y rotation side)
C1  30.48,46.99 270 top
C2  29.21,39.37 270 top
C3  53.98,33.66 270 top
C4  53.98,50.16 90 top
C5  40.01,56.52 0 top
C6  63.5,34.29 90 top
C7  58.42,34.29 90 top
C8  60.96,15.88 0 top
C9  55.88,15.88 180 top
C10  18.41,19.05 270 top
C11  22.23,15.88 180 top
C12  22.23,21.59 270 top
C13  18.41,10.16 270 top
C14  18.41,27.3 90 top
C15  33.66,11.43 180 top
C16  33.66,26.04 180 top
C17  107.95,39.37 180 top
C18  114.3,64.77 270 bottom
C19  17.78,61.59 180 top
C20  107.95,44.45 180 top
C21  151.13,7.24 270 top
C22  90.81,45.72 90 top
C23  90.81,71.12 90 top
C24  94.73,71.12 90 top
C25  33.66,15.88 0 top
C26  27.94,15.88 180 top
C27  53.34,12.7 0 top
C28  53.34,9.53 0 top
C29  72.39,73.03 180 bottom
C30  59.69,88.9 0 bottom
C31  59.69,73.03 0 bottom
C32  72.39,88.9 180 bottom
C33  62.48,91.44 180 top
C34  62.48,75.56 180 top
C35  69.6,91.44 0 top
C36  69.6,75.56 0 top
C37  144.78,8.26 180 top
C38  84.45,53.98 270 bottom
C39  22.86,61.59 180 top
C40  33.02,73.03 180 top
C41  31.75,66.67 0 top
C42  33.02,69.22 180 top
C43  130.81,60.33 180 bottom
C44  126.36,75.56 0 bottom
C45  99.69,60.96 0 bottom
C46  99.69,57.15 0 bottom
C47  77.47,5.71 0 top
C48  45.09,42.55 270 bottom
C49  48.9,32.38 0 bottom
C50  153.03,31.11 180 bottom
C51  112.39,82.55 90 top
C52  128.91,36.2 90 top
C53  40.64,79.38 180 top
F1  29.21,90.81 0 top
IC1  123.19,67.31 270 top
IC2  141.6,60.96 270 top
IC3  46.99,24.13 90 top
IC4  99.06,58.42 0 top
IC5  34.92,20.32 90 top
IC7  66.04,87 0 top
IC8  80.01,55.24 270 top
IC10  66.04,71.12 0 top
IC11  22.23,69.22 90 top
J1  10.79,90.81 0 top
JP3  97.16,76.83 180 top
JP4  114.94,40.01 270 top
KK1  66.04,71.12 180 top
KK2  66.04,87 180 top
L1  30.48,52.07 270 top
L2  87,71.12 90 top
Q1  53.98,41.91 270 top
Q2  60.96,28.57 0 top
Q3  102.23,41.91 270 top
R1  26.67,49.53 270 top
R2  24.13,46.99 90 top
R3  25.4,43.18 180 top
R4  25.4,40.64 0 top
R5  23.5,53.34 0 bottom
R6  3.81,42.55 270 bottom
R7  24.13,36.83 90 top
R8  60.96,12.7 0 top
R9  60.96,24.77 0 top
R10  23.5,11.43 180 top
R11  23.5,26.04 180 top
R12  28.57,27.3 270 top
R13  28.57,10.16 90 top
R14  33.66,8.26 0 top
R15  33.66,29.21 0 top
R16  144.78,10.79 180 top
R17  93.98,45.72 90 top
R18  48.26,9.53 0 top
R19  60.96,9.53 180 top
R20  38.73,5.71 0 top
R21  85.09,17.78 0 top
R22  85.09,20.32 0 top
R23  69.85,17.78 180 top
R24  69.85,20.32 180 top
R25  91.76,84.77 180 top
R26  91.76,82.55 0 top
SV1  62.23,46.99 90 top
SV2  77.47,22.86 270 top
U1  43.18,43.81 270 top
U$1  77.47,9.53 90 top
U$2  136.53,32.38 90 top
U$3  156.21,9.53 90 top
X1  10.79,42.55 270 top
X2  12.06,11.43 90 top
X3  12.06,26.04 90 top
X6  12.06,68.58 90 top

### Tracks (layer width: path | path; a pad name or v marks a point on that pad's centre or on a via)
!RD
  Top 0.406: IC4.34 109.89,53.3 113.03,50.16 118.11,50.16 125.73,42.55 138.43,42.55 143.51,47.62 147.96,47.62 149.86,49.53 149.86,60.33 153.03,63.5 153.03,64.77 152.4,65.41 IC2.31
!RESET  (via drill 0.6)
  Top 0.406: IC4.20 95.52,49.8 93.98,48.26 R17.2 93.98,46.99 90.81,46.99 | 90.81,46.99 C22.2 | v67.94,46.99 90.81,46.99
  Bottom 0.406: SV1.5 v67.94,46.99
!WR  (via drill 0.5)
  Top 0.406: IC4.33 109.41,52.51 113.67,48.26 v117.47,48.26 | 137.16,56.52 IC2.13 v134.62,56.52
  Bottom 0.406: v117.47,48.26 126.36,48.26 v134.62,56.52
+3V3  (via drill 0.6)
  Top 0.305: IC8.2 75.83,57.52 75.56,57.78 v74.93,57.78 | IC8.10 77.09,51.69 76.83,51.44 v74.93,51.44
  Top 0.406: R18.1 46.99,9.53 IC3.6 46.99,19.68 47.32,20.02 48.59,20.02 | v50.16,52.07 U1.28 | v50.16,40.64 U1.19 47.78,41.76 47.62,41.91 U1.20 | U1.15 v50.16,35.56 50.16,33.66 49.39,32.88 IC3.25 49.39,27.33 | IC3.29 46.19,28.74 47.6,27.33 49.39,27.33 | 52.73,27.33 52.7,27.3 | 52.73,27.33 IC3.21 49.39,27.33 | IC3.22 52.79,27.39 52.73,27.33 | 49.39,27.33 49.39,20.82 48.59,20.02 | 48.59,20.02 IC3.8 | v50.16,48.26 U1.25 | SV2.5 69.22,22.86 68.43,22.07 R24.2 R23.2 68.43,9.68 70.48,7.62 U$1.8 74.87,7.04 76.2,5.71 C47.1 | v30.48,57.15 L1.1
  Top 0.61: U$2.4 149.56,32.09 v148.59,31.11
  Top 1.27: v93.98,33.66 C52.+ v140.97,33.66
  Bottom 0.61: 50.16,59.69 50.16,60.33
  Bottom 1.27: 68.58,60.33 68.58,61.59 | 68.58,60.33 69.85,60.33 | 69.85,60.33 72.39,60.33 v74.93,57.78 v74.93,51.44 74.93,31.75 | 51.44,60.33 50.16,60.33 48.9,60.33 | 51.44,60.33 67.31,60.33 | 67.31,60.33 68.58,60.33 | 50.16,59.05 v50.16,52.07 v50.16,48.26 50.16,43.81 | 50.16,59.05 50.16,59.69 | 48.9,60.33 33.66,60.33 v30.48,57.15 | 50.16,43.81 v50.16,40.64 v50.16,35.56 50.16,32.38 C49.1 | 74.93,31.75 74.93,30.48 | 67.31,60.33 68.58,61.59 | 68.58,61.59 69.85,60.33 | 50.16,59.05 48.9,60.33 | 50.16,59.05 51.44,60.33 | v93.98,33.66 88.9,28.57 81.28,28.57 79.38,30.48 76.2,30.48 | v140.97,33.66 143.51,31.11 v148.59,31.11 C50.1 | C48.1 50.03,43.95 50.16,43.81 | 74.93,30.48 73.66,29.21 73.66,24.13 74.93,22.86 SV2.5 | 74.93,30.48 76.2,30.48 | 74.93,31.75 76.2,30.48 | 68.58,73.03 C36.+ | 68.58,73.03 IC10.OUT 68.58,61.59 | 68.58,73.03 C29.1
+5V  (via drill 0.6)
  Top 0.254: IC5.9 30.61,19.82 28.96,18.16 C26.+
  Top 0.305: IC8.19 84.19,57.52 v84.45,57.78
  Top 0.406: IC2.27 142.24,60.33 140.97,61.59 IC2.9 135.25,61.59 v133.99,62.87 | C26.+ C25.1 | IC11.16 20.32,64.77 21.46,63.63 C39.2 C19.1 19.05,61.59 v19.05,59.05 | R21.2 R22.2 86.51,22.07 85.72,22.86 81.28,22.86 80.64,23.5 | v130.81,73.03 IC1.20 | IC4.52 102.6,64.4 v103.5,63.5 103.5,60.96 96.3,53.76 IC4.21 96.3,44.87 95.73,44.3 R17.1
  Top 0.61: v88.27,80.01 88.27,84.14 88.9,84.77 R25.2
  Top 1.27: IC7.OUT 68.58,82.55 71.12,80.01 v85.72,80.01 | v137.79,10.79 R16.2 | v77.47,38.73 v72.39,38.73 | v81.28,34.29 v81.28,32.38 81.28,24.13 80.64,23.5 80.01,22.86 SV2.6 | v85.72,80.01 v87,80.01 v88.27,80.01 v87,78.74 | v87,78.74 v85.72,80.01 | v87,78.74 L2.2
  Bottom 0.406: 77.47,58.42 78.11,58.42 | 78.11,58.42 80.01,58.42 80.64,57.78 v84.45,57.78 C38.1 | 78.11,58.42 77.47,59.05 | 77.47,57.78 78.11,58.42 | 116.84,66.04 116.71,66.17 | SV2.6 77.47,21.59 77.47,17.14 73.66,13.34 31.5,13.34 C26.+
  Bottom 1.27: X6.9 9.2,72.69 7.62,71.12 7.62,61.59 8.89,60.33 14.61,60.33 15.88,59.05 v19.05,59.05 27.94,59.05 31.75,62.87 59.69,62.87 63.5,66.67 IC10.IN 63.5,73.03 | v88.27,80.01 102.23,80.01 | 102.23,80.01 103.5,80.01 | 103.5,80.01 104.78,80.01 | 104.78,80.01 C51.+ 115.57,80.01 116.84,78.74 116.84,74.3 | 118.11,73.03 127.64,73.03 | 127.64,73.03 v130.81,73.03 | 81.28,38.73 81.28,40.01 | 81.28,40.01 81.28,43.81 77.47,47.62 77.47,57.78 77.47,58.42 77.47,59.05 77.47,62.23 87,71.75 v87,78.74 | 81.28,38.73 80.01,38.73 | 80.01,38.73 v77.47,38.73 | v72.39,38.73 62.23,38.73 60.96,40.01 SV1.2 | v81.28,32.38 v81.28,34.29 81.28,37.47 | 81.28,37.47 81.28,38.73 | 103.5,60.96 v103.5,63.5 103.5,78.74 | 103.5,60.96 103.5,57.15 | 103.5,57.15 103.5,55.88 107.95,51.44 111.12,51.44 114.94,47.62 JP4.1 116.84,43.81 118.11,42.55 118.11,30.48 v137.79,10.79 | 129.54,62.87 124.46,62.87 122.56,60.96 120.02,60.96 116.84,64.14 116.84,66.04 116.84,71.75 | 129.54,62.87 v133.99,62.87 | 116.84,74.3 116.84,71.75 | 80.01,38.73 81.28,40.01 | 81.28,37.47 80.01,38.73 | 116.71,66.17 C18.1 | C43.1 129.41,62.73 129.54,62.87 | C44.1 127.77,73.16 127.64,73.03 | 103.5,60.96 C45.1 | 103.5,57.15 C46.1 | v88.27,80.01 v87,80.01 v85.72,80.01 v87,78.74 | v87,78.74 v88.27,80.01 | 116.84,74.3 118.11,73.03 | 116.84,71.75 118.11,73.03 | 103.5,80.01 103.5,78.74 | 102.23,80.01 103.5,78.74 | 103.5,78.74 104.78,80.01 | 63.5,73.03 C34.+ 63.5,76.83 68.58,81.92 IC7.OUT 68.58,88.9 | 68.58,88.9 C35.+ | 68.58,88.9 C32.1 | 63.5,73.03 C31.1
A8  (via drill 0.5)
  Top 0.406: IC4.35 110.38,54.09 112.39,52.07 v114.94,52.07 | v127.64,52.07 128.27,51.44 IC2.17
  Bottom 0.406: v114.94,52.07 v127.64,52.07
A9  (via drill 0.5)
  Top 0.406: IC4.36 112.13,54.88 v113.03,53.98 | v123.19,53.98 127,50.16 IC2.18 137.16,50.16
  Bottom 0.406: v113.03,53.98 v123.19,53.98
A10
  Top 0.406: IC4.37 113.88,55.66 125.73,43.81 138.43,43.81 143.51,48.9 147.96,48.9 148.59,49.53 148.59,50.8 147.96,51.44 IC2.20
A11
  Top 0.406: IC4.38 114.36,56.45 125.73,45.09 138.43,45.09 143.51,50.16 143.51,52.07 144.15,52.7 IC2.21
A12
  Top 0.406: IC4.39 114.85,57.24 125.73,46.35 138.43,46.35 142.24,50.16 142.24,52.07 144.15,53.98 IC2.22
A13
  Top 0.406: IC4.40 115.33,58.03 125.73,47.62 138.43,47.62 140.97,50.16 140.97,52.07 144.15,55.24 IC2.23
A14
  Top 0.406: IC4.41 115.81,58.81 125.73,48.9 138.43,48.9 139.7,50.16 139.7,52.07 144.15,56.52 IC2.24
AD0
  Top 0.406: IC4.51 103.39,67.83 104.78,69.22 111.76,69.22 114.3,71.75 IC1.2 119.38,71.75 120.02,72.39 120.02,73.66 124.46,78.11 137.79,78.11 142.88,73.03 142.88,64.77 142.24,64.14 IC2.7
AD1  (via drill 0.5)
  Top 0.406: IC4.50 104.18,67.35 104.78,67.94 111.76,67.94 114.3,70.48 IC1.3 120.02,70.48 121.28,71.75 121.28,73.66 124.46,76.83 137.79,76.83 141.6,73.03 v141.6,66.04 | 136.53,62.87 IC2.8 v141.6,62.87
  Bottom 0.406: v141.6,66.04 v141.6,62.87
AD2  (via drill 0.5)
  Top 0.406: IC4.49 111.27,66.18 114.3,69.22 IC1.4 120.65,69.22 122.56,71.12 122.56,73.66 124.46,75.56 137.79,75.56 140.34,73.03 v140.34,67.31 | v140.34,59.05 IC2.11
  Bottom 0.406: v140.34,67.31 v140.34,59.05
AD3  (via drill 0.5)
  Top 0.406: IC4.48 110.68,64.33 114.3,67.94 IC1.5 121.28,67.94 123.83,70.48 123.83,73.66 124.46,74.3 137.79,74.3 139.06,73.03 v139.06,66.04 | v139.06,57.78 IC2.12
  Bottom 0.406: v139.06,66.04 v139.06,57.78
AD4  (via drill 0.5)
  Top 0.406: IC4.47 111.16,63.54 114.3,66.67 IC1.6 v125.09,66.67 | v141.6,57.78 IC2.25
  Bottom 0.406: v125.09,66.67 137.79,66.67 140.34,69.22 141.6,69.22 142.88,67.94 142.88,62.23 141.6,60.96 v141.6,57.78
AD5  (via drill 0.5)
  Top 0.406: IC4.46 111.65,62.75 114.3,65.41 IC1.7 v123.83,65.41 | 146.05,59.05 IC2.26 v148.59,59.05
  Bottom 0.406: v123.83,65.41 123.83,67.94 124.46,68.58 137.79,68.58 139.7,70.48 144.78,70.48 148.59,66.67 v148.59,59.05
AD6  (via drill 0.5)
  Top 0.406: IC4.45 112.13,61.96 114.3,64.14 IC1.8 v122.56,64.14 | 146.05,62.87 IC2.29 v149.86,62.87
  Bottom 0.406: v122.56,64.14 122.56,68.58 123.83,69.85 137.16,69.85 139.06,71.75 145.41,71.75 149.86,67.31 v149.86,62.87
AD7  (via drill 0.5)
  Top 0.406: IC4.44 112.61,61.18 114.3,62.87 IC1.9 v121.28,62.87 | v151.13,64.14 IC2.30
  Bottom 0.406: v121.28,62.87 121.28,69.22 123.19,71.12 136.53,71.12 138.43,73.03 146.05,73.03 151.13,67.94 v151.13,64.14
ALE
  Top 0.406: IC4.43 125.16,60.39 126.36,61.59 IC1.11 128.27,61.59
BS0
  Top 0.406: IC4.57 98.67,68.82 104.14,74.3 111.76,74.3 120.65,83.19 137.79,83.19 144.15,76.83 147.96,76.83 152.4,72.39 152.4,71.12 147.96,66.67 IC2.32
BS1
  Top 0.406: IC4.56 99.45,68.34 104.14,73.03 111.76,73.03 120.65,81.92 137.79,81.92 144.15,75.56 147.96,75.56 151.13,72.39 151.13,71.12 147.96,67.94 IC2.33
BS2
  Top 0.406: IC4.55 100.24,67.86 104.14,71.75 111.76,71.75 120.65,80.64 137.79,80.64 144.15,74.3 147.96,74.3 149.86,72.39 149.86,71.12 147.96,69.22 IC2.34
BS3
  Top 0.406: IC4.54 101.03,67.37 104.14,70.48 111.76,70.48 120.65,79.38 137.79,79.38 144.15,73.03 147.96,73.03 148.59,72.39 148.59,71.12 147.96,70.48 IC2.35
BUTTON
  Top 0.406: IC4.59 97.09,73.41 95.89,74.61 JP3.3
CS_ENC
  Top 0.305: IC4.10 87.72,57.24 86.7,56.22 IC8.17
CS_SD
  Top 0.305: IC4.4 83.55,61.96 81.28,59.69 81.28,57.78 82.19,56.87 IC8.18
CS_STA
  Top 0.305: IC4.5 84.04,61.18 82.93,60.07 IC8.20
ENC_INT
  Top 0.305: IC8.8 68.3,53.62 66.04,55.88 47.62,55.88 40.01,48.26 U1.4
GND  (via drill 0.6)
  Top 0.406: IC2.28 146.05,61.59 | 54.3,25.73 IC3.19 51.1,25.73 v50.8,26.04 | IC3.30 45.39,31.45 | 46.19,20.16 IC3.5 46.19,16.34 v45.09,15.24 | IC4.53 101.82,64.77 101.6,64.77 100.33,63.5 v97.16,63.5 | 93.94,64.77 IC4.63 93.94,67.94 | 97.09,52.07 IC4.22 97.09,43.75 95.89,42.55 91.44,42.55 90.81,43.18 C22.1 | IC3.7 47.79,15.71 v48.26,15.24
  other vias: 115.57,61.59 118.75,74.93 134.62,60.33 144.15,61.59 36.2,40.64 43.81,46.35 45.09,21.59 45.09,32.38 81.92,49.53 134.62,64.77 88.9,41.91 94.61,38.73 102.23,53.98 93.98,62.23 96.52,57.15 99.06,53.34 45.72,39.37 45.09,46.35 52.07,40.64 22.86,67.31 38.1,66.67 31.11,43.18 52.07,53.98 64.77,9.53 64.77,15.88 67.94,26.04 69.22,32.38 84.45,26.04 112.39,15.24 83.82,6.35 107.95,41.91 128.91,38.1 145.41,41.91 157.48,30.48 108.58,76.83 149.86,87 77.47,15.24
  pour Top (isolate 0.406): 0,95.25 160.02,95.25 160.02,4.45 39.37,4.45 39.37,34.29 0,34.29
  pour Bottom (isolate 0.406): 0,95.25 160.02,95.25 160.02,4.45 39.37,4.45 39.37,34.29 0,34.29
GNDA
  Top 0.254: IC5.8 33.02,20.32 | 29.21,20.32 IC5.8 | IC5.8 33.89,20.32
  pour Bottom (isolate 0.406): 0.64,4.45 0.64,33.02 38.1,33.02 38.1,4.45
  pour Top (isolate 0.406): 0.64,4.45 0.64,33.02 38.1,33.02 38.1,4.45
INT4  (via drill 0.6)
  Top 0.305: IC8.12 85.46,52.97 v87.63,50.8
  Top 0.406: IC4.6 93.92,60.39 v94.61,59.69
  Bottom 0.406: v87.63,50.8 90.81,50.8 94.61,54.61 v94.61,59.69
INT5  (via drill 0.6)
  Top 0.305: IC8.13 86.72,53.62 v87.63,52.7
  Top 0.406: IC4.7 92.8,59.6 93.34,59.05 v93.34,57.78
  Bottom 0.406: v93.34,57.78 93.34,54.61 91.44,52.7 v87.63,52.7
INT6  (via drill 0.6)
  Top 0.406: v80.01,60.96 79.38,61.59 48.26,61.59 38.73,71.12 v37.47,71.12 | v31.75,76.83 24.13,76.83 20.95,73.66 IC11.9 | v84.45,59.69 87,59.69 87.87,58.81 IC4.8
  Bottom 0.406: v31.75,76.83 v37.47,71.12 | v84.45,59.69 81.28,59.69 v80.01,60.96
IR_RX  (via drill 0.6)
  Top 0.406: v86.36,30.48 92.08,24.77 139.7,24.77 151.13,13.34 U$3.OUT | IC4.9 86.6,58.03 v86.36,57.78
  Bottom 0.406: v86.36,30.48 v86.36,57.78
LED
  Top 0.406: IC4.58 97.88,69.3 100.97,72.39 JP3.1
MISO
  Top 0.305: IC4.13 89.17,54.88 88.56,54.27 IC8.14 81.58,54.27 81.28,53.98 81.28,52.07 78.11,48.9 67.94,48.9 66.04,46.99 66.04,42.55 64.14,40.64 62.87,40.64 62.23,41.27 62.23,50.8 SV1.9
MOSI
  Top 0.305: IC4.12 88.68,55.66 87.94,54.92 IC8.15 80.95,54.92 80.01,53.98 80.01,52.07 77.47,49.53 67.31,49.53 65.41,47.62 65.41,43.81 SV1.1
N$1
  Top 0.406: 137.16,71.75 IC2.1 IC1.19
N$2
  Top 0.406: 137.16,70.48 IC2.2 IC1.18
N$3
  Top 0.406: IC1.17 IC2.3
N$4
  Top 0.406: IC1.16 IC2.4
N$5
  Top 0.406: 137.16,66.67 IC2.5 IC1.15
N$6
  Top 0.406: IC1.14 129.54,65.41 132.72,62.23 132.72,56.52 133.99,55.24 IC2.14
N$7
  Top 0.406: IC1.13 129.54,64.14 131.44,62.23 131.44,56.52 133.99,53.98 IC2.15 137.16,53.98
N$8
  Top 0.406: IC1.12 129.54,62.87 130.18,62.23 130.18,56.52 133.99,52.7 IC2.16 137.16,52.7
N$9  (via drill 0.6)
  Top 0.406: X1.1 20.95,50.8 R1.1 | v44.45,38.1 U1.17
  Bottom 0.406: R1.1 31.75,50.8 v44.45,38.1
N$10  (via drill 0.6)
  Top 0.406: v45.72,36.83 U1.16 | R2.1 22.86,45.72 21.59,44.45 X1.3
  Bottom 0.406: R2.1 34.92,45.72 43.81,36.83 v45.72,36.83
N$11  (via drill 0.6)
  Top 0.406: v31.75,36.83 U1.13 | X1.4 R3.2
  Bottom 0.406: R3.2 25.4,41.91 25.4,39.37 27.94,36.83 v31.75,36.83
N$12
  Top 0.406: U1.12 33.02,38.1 31.75,39.37 25.4,39.37 R4.1 X1.6
N$13
  Top 0.406: X1.2 22.23,48.26 R2.2 R1.2 30.48,48.26 C1.1 L1.2
N$14
  Bottom 0.406: X1.R_YEL_A 5.36,35.92 3.81,37.47 R6.2
N$15
  Top 0.406: R3.1 R4.2 29.21,40.64 C2.1
N$16  (via drill 0.6)
  Top 0.406: v43.18,48.26 45.72,50.8 U1.27
  Bottom 0.406: R5.1 38.1,53.34 v43.18,48.26
N$17  (via drill 0.6)
  Top 0.406: v45.09,48.26 46.35,49.53 U1.26
  Bottom 0.406: R6.1 3.81,48.26 8.26,52.7 18.41,52.7 20.95,55.24 38.1,55.24 v45.09,48.26
N$18
  Bottom 0.406: X1.L_GRN_A 8.89,51.44 18.52,51.44 20.43,53.34 R5.2
N$19
  Top 0.406: U1.24 53.34,46.99 | 53.34,46.99 53.98,47.62 | 53.98,46.35 Q1.1 | 53.34,46.99 53.98,46.35 | 53.98,46.35 53.98,46.99 | 53.98,46.99 C4.1 | 53.34,46.99 53.98,46.99
N$20
  Top 0.406: U1.23 49.53,45.72 53.98,41.27 Q1.2 | Q1.2 53.98,39.37 | 53.98,34.92 C3.1 Q1.2
N$21
  Top 0.406: R7.1 U1.14
N$22
  Top 0.406: C5.+ 38.99,52.07 U1.1
N$23
  Bottom 1.27: J1.3 F1.1
N$24  (via drill 0.6)
  Top 0.406: IC11.8 25.4,73.66 v23.5,71.75
  Bottom 0.406: X6.7 18.95,67.21 v23.5,71.75
N$25
  Top 0.406: IC3.15 58.73,22.53 59.54,23.34 R9.1 59.54,26.19 58.55,27.18 Q2.1 58.55,32.89 58.42,33.02 C7.1
N$26
  Top 0.406: IC3.13 60.3,20.93 62.38,23.01 R9.2 62.38,26.19 63.37,27.18 Q2.2 63.37,32.89 63.5,33.02 C6.1
N$27
  Top 0.406: C8.1 C9.1 57.28,17.65 54.8,20.13 IC3.12
N$28
  Top 0.254: IC5.1 42.18,19.32 43.18,20.32 43.18,20.95 42.41,21.73 IC3.42
N$29
  Top 0.254: IC5.2 38.23,19.82 | 38.23,19.82 | IC3.44 38.55,20.13 38.23,19.82
N$30
  Top 0.254: IC5.3 36.2,20.32 35.56,19.68 35.56,19.05 36.2,18.41 40.01,18.41 41.91,16.51 43.18,16.51 43.79,17.12 IC3.2
N$31
  Top 0.254: IC5.4 35.42,20.82 34.92,20.32 34.92,18.41 35.56,17.78 39.37,17.78 41.27,15.88 43.81,15.88 44.59,16.65 IC3.3
N$32
  Top 0.406: C8.2 62.23,15.88 62.38,15.72 R8.2
N$33  (1 unrouted)
  Top 0.254: IC5.5 37.04,22.61
  Top 0.406: C12.+ 19.43,22.61 18.41,21.59 C10.1
  Bottom 0.406: C12.+ 37.04,22.61
N$34
  Top 0.254: IC5.6 26.4,21.32 23.24,18.16 C11.+
N$35
  Top 0.406: 19.05,26.04 C14.1
  Top 0.813: R11.2 19.05,26.04 X3.1
N$36
  Top 0.406: 18.41,11.43 C13.1
  Top 0.813: R10.2 18.41,11.43 X2.1
N$37
  Top 0.406: IC4.23 97.88,42.46 100.84,39.5 Q3.2 106.55,39.5 106.68,39.37 C17.2
N$38
  Top 0.406: R10.1 24.77,11.43 | 28.57,11.43 R13.2
  Top 0.813: C15.2 28.57,11.43 R10.1
N$39
  Top 0.406: R11.1 24.77,26.04 | 28.57,26.04 R12.2
  Top 0.813: C16.2 28.57,26.04 R11.1
N$40
  Top 0.254: C15.1 35.05,12.57 33.66,13.97 33.66,17.14 32.81,17.99 IC5.10
  Top 0.813: R14.2 34.92,8.26 35.05,8.38 C15.1
N$41
  Top 0.254: IC5.7 33.52,20.82 35.05,22.36 C16.1
  Top 0.813: R15.2 34.92,29.21 35.05,29.08 C16.1
N$42
  Top 0.61: R25.1 93.18,82.7 93.03,82.55 R26.2 93.34,82.55 JP3.4
N$44
  Top 0.406: IC4.24 98.67,46.11 100.46,44.32 Q3.1 106.55,44.32 106.68,44.45 C20.2
N$45
  Top 0.406: U$3.V+ C21.+ 146.05,8.25 146.05,8.26 C37.1 146.18,10.66 146.05,10.79 R16.1
N$46  (via drill 0.6)
  other vias: 37.04,22.61
N$47
  Top 0.406: IC4.64 88.12,66.18 87,67.31 L2.1 90.1,69.92 90.17,69.85 C23.1
N$48
  Top 0.406: IC3.10 50.19,13.31 50.8,12.7 C27.1 52.07,12.7 51.94,12.57 C28.1 R18.2 49.53,9.53
N$49
  Top 0.406: 94.73,69.74 94.73,69.73 C24.1 | IC4.62 94.73,69.74 | 94.73,69.74 94.61,69.85
N$51
  Bottom 1.27: 63.5,88.9 IC7.IN 63.5,82.55 60.33,79.38 C53.+ 40.46,82.09 F1.2 | 63.5,88.9 C33.+ | 63.5,88.9 C30.1
N$56
  Top 0.406: C41.2 33.15,65.53 32.38,64.77 IC11.1
N$57
  Top 0.406: IC11.3 28.57,67.31 29.21,66.67 C41.1
N$58
  Top 0.406: IC11.4 29.21,68.58 29.84,69.22 C42.2
N$59
  Top 0.406: C42.1 34.42,70.36 33.66,71.12 30.48,71.12 29.21,69.85 IC11.5
N$60
  Top 0.406: IC11.2 25.4,66.04 24.26,64.9 C39.1
N$61
  Top 0.406: IC11.6 28.57,71.12 30.48,73.03 C40.2
N$62
  Top 0.406: X6.2 14.81,67.31 IC11.14
N$63
  Top 0.406: X6.3 IC11.13
PVSS
  Top 0.406: IC3.11 50.99,16.95 52.07,15.88 C9.2 54.61,15.88 54.74,15.74 C27.2 | R8.1 59.69,12.7 | C27.2 R8.1 | C28.2 54.61,9.53 54.74,9.65 C27.2 | R8.1 R19.2 59.69,9.53
RXD0
  Top 0.406: IC4.2 48.86,63.54 34.29,78.11 23.5,78.11 20.32,74.93 15.88,74.93 15.24,74.3 15.24,70.48 15.88,69.85 IC11.12
RXD1
  Top 0.406: IC4.27 101.03,49.47 102.87,47.62 109.86,47.62 111.12,46.35 111.12,40.64 113.03,38.73 JP4.3
SCK
  Top 0.305: IC4.11 88.2,56.45 87.32,55.57 IC8.16 80.33,55.57 78.74,53.98 78.74,52.07 76.83,50.16 66.67,50.16 66.04,49.53 SV1.7
SCL  (via drill 0.6)
  Top 0.406: U$1.2 83.82,8.89 85.09,10.16 85.09,18.9 R22.1 | IC4.25 99.45,47.87 v100.33,46.99 | R22.1 83.82,20.32 | R22.1 SV2.8
  Bottom 0.406: v100.33,46.99 100.33,34.29 86.36,20.32 SV2.8
SCL_3,3V  (via drill 0.6)
  Top 0.406: U$1.7 71.12,8.89 69.85,10.16 69.85,18.9 R24.1 SV2.7 | IC3.32 43.79,26.7 v46.35,24.13
  Bottom 0.406: v46.35,24.13 57.15,24.13 60.96,20.32 SV2.7
SD_DETECT  (via drill 0.6)
  Top 0.406: v83.82,49.53 88.27,49.53 88.9,50.16 88.9,53.34 89.65,54.09 IC4.14 | U$2.12 92.56,21.73 v83.82,30.48
  Bottom 0.406: v83.82,30.48 v83.82,49.53
SDA  (via drill 0.6)
  Top 0.406: U$1.3 83.19,10.16 83.67,10.64 R21.1 | IC4.26 100.24,48.98 v102.87,46.35 | R21.1 83.82,17.78 | R21.1 SV2.10
  Bottom 0.406: v102.87,46.35 104.14,45.09 104.14,36.83 85.09,17.78 SV2.10
SDA_3,3V  (via drill 0.6)
  Top 0.406: U$1.6 71.75,10.16 71.27,10.64 R23.1 SV2.9 | IC3.31 44.59,27.8 48.26,24.13 v48.26,21.59
  Bottom 0.406: v48.26,21.59 56.52,21.59 60.33,17.78 SV2.9
SPI_CS_ENC
  Top 0.305: IC8.4 74.59,56.22 72.39,58.42 46.99,58.42 43.81,61.59 36.2,61.59 34.29,59.69 34.29,44.45 36.83,41.91 U1.9
SPI_CS_SD  (via drill 0.6)
  Top 0.305: v79.38,56.87 IC8.3
  Top 0.406: U$2.1 149.44,39.59 139.7,29.84 95.25,29.84 82.55,42.55 v82.55,45.72
  Bottom 0.406: v82.55,45.72 79.38,48.9 v79.38,56.87
SPI_CS_STA  (via drill 0.6)
  Top 0.305: IC8.1 77.09,58.8 76.83,59.05 47.62,59.05 44.45,62.23 35.56,62.23 33.66,60.33 v33.66,41.27
  Top 0.406: IC3.38 v43.18,24.93
  Bottom 0.406: v33.66,41.27 43.18,31.75 v43.18,24.93
SPI_SCK  (via drill 0.6)
  Top 0.305: IC8.5 73.33,55.57 v72.39,56.52 71.12,57.78 46.35,57.78 43.18,60.96 36.83,60.96 34.92,59.05 34.92,45.09 36.83,43.18 U1.8
  Top 0.406: U1.8 40.01,43.18 40.64,42.55 40.64,31.11 39.37,29.84 39.37,27.3 40.15,26.53 IC3.36 | U$2.5 150.12,29.59 147.96,27.3 93.98,27.3 76.83,44.45 v72.39,44.45
  Bottom 0.406: v72.39,56.52 v72.39,44.45
SPI_SI  (via drill 0.6)
  Top 0.305: IC8.6 71.44,54.92 v70.48,55.88 69.22,57.15 45.72,57.15 42.55,60.33 37.47,60.33 35.56,58.42 35.56,45.72 36.83,44.45 U1.7
  Top 0.406: U1.7 40.64,44.45 41.91,43.18 41.91,30.48 41.19,29.76 IC3.34 | U$2.2 150.12,37.09 141.6,28.57 94.61,28.57 77.47,45.72 v70.48,45.72
  Bottom 0.406: v70.48,55.88 v70.48,45.72
SPI_SO  (via drill 0.6)
  Top 0.305: IC8.7 69.56,54.27 v68.58,55.24 67.31,56.52 45.09,56.52 41.91,59.69 38.1,59.69 36.2,57.78 36.2,46.35 36.83,45.72 U1.6
  Top 0.406: U$2.7 150.04,24.59 148.59,26.04 93.34,26.04 76.2,43.18 70.48,43.18 v69.22,44.45
  Bottom 0.406: v68.58,55.24 68.58,48.9 69.22,48.26 v69.22,44.45
STA_DATAREQ
  Top 0.305: IC8.9 67.68,52.97 65.41,55.24 48.26,55.24 41.27,48.26 41.27,45.72 43.18,43.81 43.18,36.83 47.79,32.22 IC3.27
TXD0
  Top 0.406: IC4.3 48.37,62.75 35.56,75.56 24.13,75.56 19.68,71.12 IC11.11
TXD1
  Top 0.406: IC4.28 101.82,49.95 102.87,48.9 109.86,48.9 112.39,46.35 112.39,41.91 113.03,41.27 JP4.2

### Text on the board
Top: LED | Taster | 5V | TX | ISP | RX | GND | I²C | USART1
